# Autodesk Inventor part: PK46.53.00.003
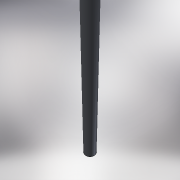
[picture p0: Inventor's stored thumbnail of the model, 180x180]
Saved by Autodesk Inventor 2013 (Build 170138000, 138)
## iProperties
Created: 2005-03
Part Number: PK46.53.00.003
Material: Steel, Mild
Document SubType Name: Modeling
Designer: HKostja
Manufacturer: Standard
Standards Organization: Custom
Density: 7.86 g/cm^3
Mass: 2270.61 g
Surface Area: 1660.98 cm^2
Volume: 288.881 cm^3
Author: HKostja
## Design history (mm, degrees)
sketch "Эскиз1"
  geometry: C1 r 25 at (0, 0); C2 r 21.5 at (0, 0)
  constraints: 2 centre point, 1 coincident, 1 other
  dimensions: "d0" = 3.5 radial gap between concentric circles of C1 C2; "d1" = 50 diameter of C1
extrude "Выдавливание2" new body sketch "Эскиз1" distance "d8" = 565; taper "d9" = 0 deg
body "Solid1"
